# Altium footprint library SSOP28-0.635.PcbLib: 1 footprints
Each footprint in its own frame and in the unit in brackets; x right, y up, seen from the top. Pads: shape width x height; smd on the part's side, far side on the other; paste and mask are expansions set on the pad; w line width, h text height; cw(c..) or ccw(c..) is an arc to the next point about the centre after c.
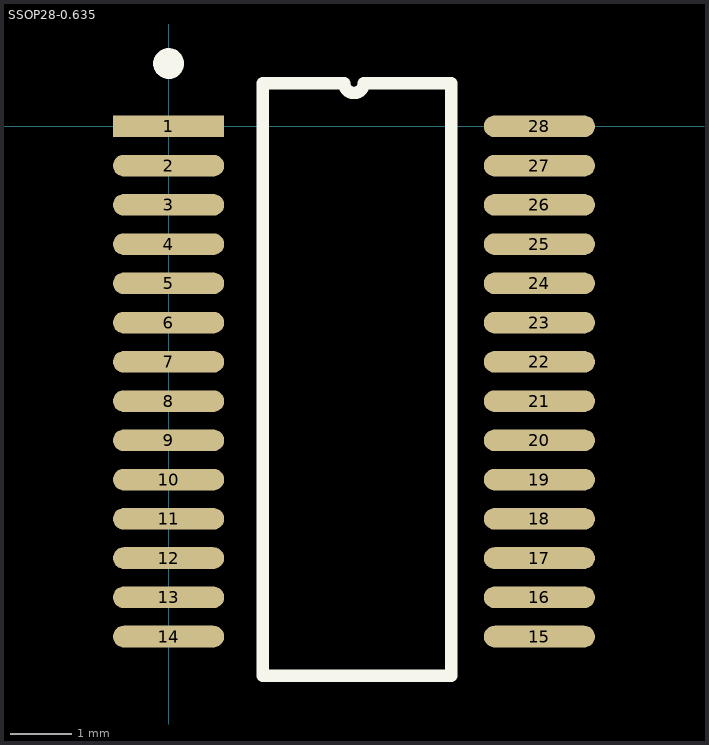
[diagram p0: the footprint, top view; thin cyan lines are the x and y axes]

## SSOP28-0.635 [mm]
pads (28):
  rect 1.8x0.35 smd: 1(0,0)
  oval 1.8x0.35 smd: 2(0,-0.635) 3(0,-1.27) 4(0,-1.905) 5(0,-2.54) 6(0,-3.175) 7(0,-3.81) 8(0,-4.445) 9(0,-5.08) 10(0,-5.715) 11(0,-6.35) 12(0,-6.985) 13(0,-7.62) 14(0,-8.255) 15(6,-8.255) 16(6,-7.62) 17(6,-6.985) 18(6,-6.35) 19(6,-5.715) 20(6,-5.08) 21(6,-4.445) 22(6,-3.81) 23(6,-3.175) 24(6,-2.54) 25(6,-1.905) 26(6,-1.27) 27(6,-0.635) 28(6,0)
Top Overlay:
  circle w0.25: c0,1.016 r0.125
  lines w0.2: 1.524,-8.89 1.524,0.699 2.841,0.699 ccw(c3,0.699) 3.159,0.699 4.572,0.699 4.572,-8.89 1.524,-8.89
